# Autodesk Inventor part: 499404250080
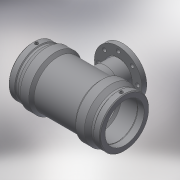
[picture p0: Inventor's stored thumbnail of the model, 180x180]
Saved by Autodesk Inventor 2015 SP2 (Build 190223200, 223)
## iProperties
Created: 2017-06
Part Number: 499404250080
Material: Generic
Description: PLASSON FLANGED TEE 250x80x250
Document SubType Name: Modeling
Designer: KIM
Mass: 57.3761 g
Surface Area: 241.06 cm^2
Volume: 57.3761 cm^3
Density: 1 g/cm^3
Appearance: Default
Author: KIM
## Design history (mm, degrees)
derived "499404.ipt"
feature "Solid1::499404.ipt"
tag "TaggingFeature1"
body "Solid1"
other parameters: "d13" = 538, "d14" = 17.6296, "d17" = 225, "d19" = 3.52592, "d20" = 168 deg, "d22" = 303.18, "d23" = 326, "d24" = 294.0846, "d25" = 135 deg, "d26" = 376.6, "d27" = 135 deg, "d29" = 152, "d35" = 15, "d39" = 5 deg, "d45" = 4, "d46" = 14, "d47" = 0, "d55" = 293.4, "d56" = 326, "d57" = 188.3, "d58" = 135 deg, "d59" = 129, "d60" = 129, "d61" = 135 deg, "d72" = 244.79, "d73" = 122.395, "d87" = 138, "d89" = 96, "d91" = 15 deg, "d92" = 104, "d95" = 4.14, "d97" = 18, "d100" = 0, "d102" = 360 deg, "d105" = 0, "d107" = 0, "d108" = 3, "d109" = 0, "d110" = 38.7, "d111" = 12.9, "L_" = 538, "L_1" = 129, "D_" = 326, "A_" = 152, "d_2" = 12, "d_1" = 138, "s_" = 18
